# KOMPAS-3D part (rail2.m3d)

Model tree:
1. X Axis
2. Y Axis
3. Z Axis
4. Origin  (labels: rail2)
     Wall Thickness 1 = 1; Wall Thickness 2 = 1; Distance 1 = 50; Distance 2 = 10

Referenced files in C:\Work\01 К О М П А С\Модели примеры\2009_04_For_Poland_AXAPACK\My sample\Box_sample\: Side plate.a3d
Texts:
  rail2
  Steel DIN 17102
  Three Point Plane
  Plane at Angle
  Line and Point Plane
  Axis through Two Vertices
  Axis of Feature
  Axis of Conical Surface
  Axis through Edge
  Trim by Surface
  Trim by Sketch
  Feature with No History
  Intersection Axis of Two Planes
  Two Line Plane
  Line and Face Plane
  Bend by line
  Hole in sheet body
  Cut in sheet body
  Point in CM
  Linear Dimension from Line to Point
  Surface Finish Symbol
  Geometric Tolerance Symbol
  Leader #1
  Leader #2
  Leader #3
  Shape Deviations and Datum
  Node point number
  Mark of coordination axis
  Node point designation
  Mark/Reference designation with leader
  Mark/reference designation on line
  Mark/Reference designation without leader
